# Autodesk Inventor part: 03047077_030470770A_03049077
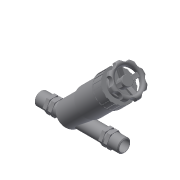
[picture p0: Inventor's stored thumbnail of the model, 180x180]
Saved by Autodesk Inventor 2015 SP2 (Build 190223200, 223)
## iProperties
Created: 2017-05
Part Number: 03047077_030470770A_03049077
Material: Generic
Description: PLASSON ANGLE SEAT VALVE 3/4"-3/4"
Document SubType Name: Modeling
Designer: KIM
Density: 1 g/cm^3
Appearance: Default
Author: KIM
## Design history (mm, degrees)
derived "03049.ipt"
feature "Solid1::03049.ipt"
tag "TaggingFeature1"
body "Solid1"
other parameters: "d0" = 151, "d1" = 26.441, "d2" = 27, "d3" = 21.1528, "d4" = 18, "d5" = 18, "d6" = 15.1, "d8" = 1.51, "d12" = 0, "d14" = -7.55, "d15" = 3.02, "d16" = 0, "d17" = 35.937, "d18" = 4.356, "d19" = 119.79, "d20" = 43.56, "d21" = 135 deg, "d22" = 46.2825, "d23" = 21.78, "d24" = 51.7275, "d25" = 13.068, "d26" = 90 deg, "d27" = 38.115, "d28" = 70 deg, "d29" = 16.335, "d30" = 13.068, "d31" = 16.335, "d32" = 54.45, "d33" = 38.115, "d34" = 135 deg, "d35" = 2, "d36" = 108.9, "d39" = 52.85, "d40" = 1.21, "d41" = 1, "d42" = 1, "d43" = 3.63, "d44" = 3.63, "d46" = 0, "d48" = 360 deg, "d50" = 0.605, "d51" = 0.605, "d53" = 360 deg, "d69" = 46.2825, "d70" = 3.63, "d71" = 3.63, "d72" = 7.26, "d74" = 0, "d75" = 0.605, "d77" = 360 deg, "d80" = 50.17568, "d81" = 4.84, "d82" = 2.42, "d83" = 19.602, "d84" = 0, "d86" = 360 deg, "d88" = 1.21, "d91" = 121, "H_" = 151, "R_" = 26.441, "E_" = 27, "l_2" = 18, "A_" = 121, "d13" = 15.1, "d67" = 54.45, "d68" = 38.115, "d79" = 51.7275
